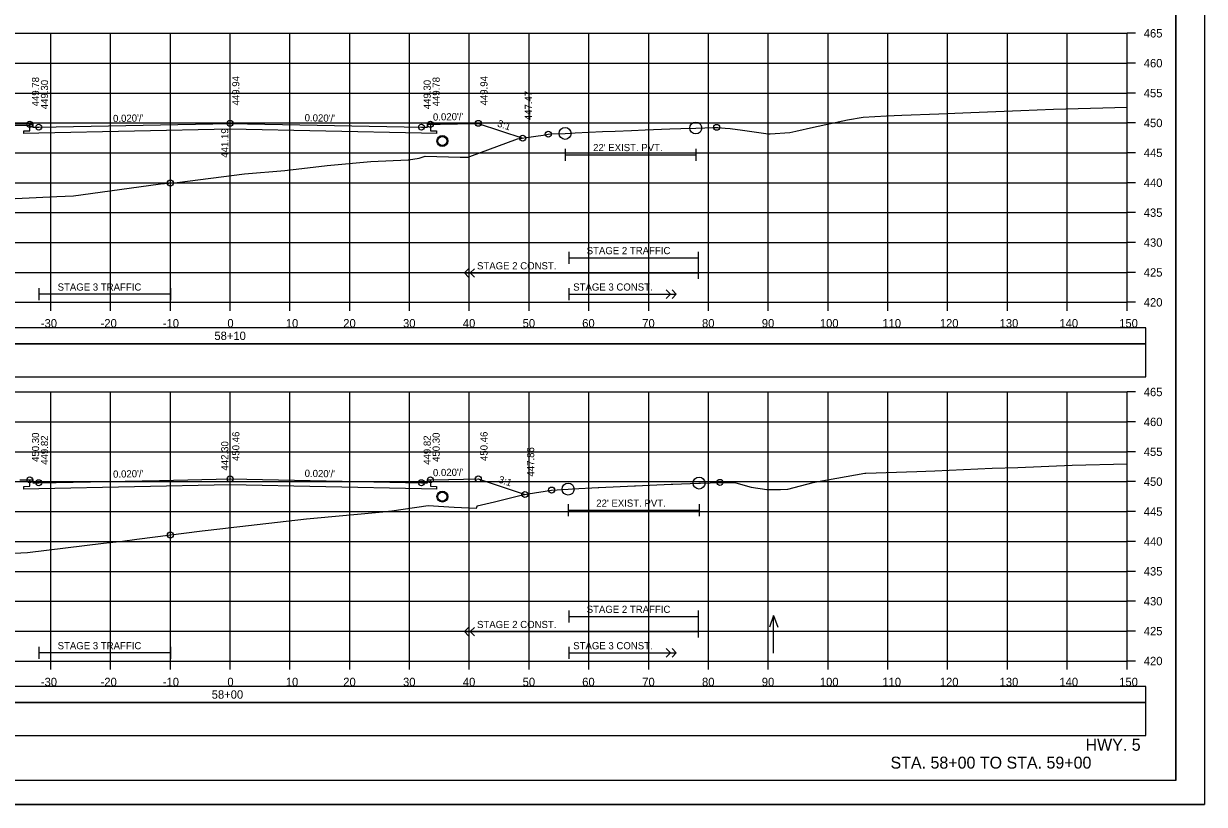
# Model space of a CAD drawing. Extents: x 1371057 to 1372761, y 380005 to 390517.
# Drawn here: x 1371526.3 to 1371723.8, y 384271.8 to 384402.4 of the extents above; entities that cross this region are included whole.
import ezdxf

# ---------------------------------------------------------------- set-up
doc = ezdxf.new("R2010")
doc.units = 0
for name, color, linetype in [('R_Alt Surface', 7, 'Continuous'), ('R_Axis', 7, 'Continuous'), ('R_Axis Annot', 7, 'Continuous'), ('R_Border', 7, 'Continuous'), ('R_Detour', 7, 'Continuous'), ('R_Dimension', 7, 'Continuous'), ('R_Draft', 7, 'Continuous'), ('R_Drive', 7, 'Continuous'), ('R_Exist Surface', 7, 'Continuous'), ('R_Fin Surface', 7, 'Continuous'), ('R_Grid', 7, 'Continuous'), ('R_No Plot', 7, 'Continuous'), ('R_Striping', 7, 'Continuous'), ('R_Water', 7, 'Continuous'), ('R_Water Annot', 7, 'Continuous'), ('R_Xsect Elev', 7, 'Continuous'), ('R_Xsect Slope', 7, 'Continuous')]:
    doc.layers.add(name, color=color, linetype=linetype)

msp = doc.modelspace()

# ---------------------------------------------------------------- linework, layer by layer
at = {"layer": 'R_Alt Surface'}
for points in [[(1371594.37, 384385.6), (1371594.37, 384384.52), (1371595.37, 384384.5), (1371595.37, 384384.07), (1371592.87, 384384.12), (1371560.87, 384384.76), (1371528.87, 384384.12), (1371526.37, 384384.07), (1371526.37, 384384.5), (1371527.37, 384384.52), (1371527.37, 384385.6)], [(1371616.88, 384381.51), (1371616.88, 384379.51)], [(1371638.75, 384381.51), (1371638.75, 384379.51)], [(1371616.88, 384380.51), (1371638.75, 384380.51)], [(1371594.37, 384326.12), (1371594.37, 384325.04), (1371595.37, 384325.02), (1371595.37, 384324.59), (1371592.87, 384324.64), (1371560.87, 384325.28), (1371528.87, 384324.64), (1371526.37, 384324.59), (1371526.37, 384325.02), (1371527.37, 384325.04), (1371527.37, 384326.12)], [(1371617.4, 384322.03), (1371617.4, 384320.03)], [(1371639.29, 384322.03), (1371639.29, 384320.03)], [(1371617.4, 384321.03), (1371639.29, 384321.03)]]:
    msp.add_lwpolyline(points, dxfattribs=at)
at = {"layer": 'R_Axis'}
for p, q in [((1371710.87, 384355.82), (1371710.87, 384400.82)), ((1371712.27, 384400.82), (1371710.87, 384400.82)), ((1371712.27, 384395.82), (1371710.87, 384395.82)), ((1371712.27, 384390.82), (1371710.87, 384390.82)), ((1371712.27, 384385.82), (1371710.87, 384385.82)), ((1371712.27, 384380.82), (1371710.87, 384380.82)), ((1371712.27, 384375.82), (1371710.87, 384375.82)), ((1371712.27, 384370.82), (1371710.87, 384370.82)), ((1371712.27, 384365.82), (1371710.87, 384365.82)), ((1371712.27, 384360.82), (1371710.87, 384360.82)), ((1371410.87, 384355.82), (1371710.87, 384355.82)), ((1371530.87, 384354.42), (1371530.87, 384355.82)), ((1371540.87, 384354.42), (1371540.87, 384355.82)), ((1371550.87, 384354.42), (1371550.87, 384355.82)), ((1371560.87, 384354.42), (1371560.87, 384355.82)), ((1371570.87, 384354.42), (1371570.87, 384355.82)), ((1371580.87, 384354.42), (1371580.87, 384355.82)), ((1371590.87, 384354.42), (1371590.87, 384355.82)), ((1371600.87, 384354.42), (1371600.87, 384355.82)), ((1371610.87, 384354.42), (1371610.87, 384355.82)), ((1371620.87, 384354.42), (1371620.87, 384355.82)), ((1371630.87, 384354.42), (1371630.87, 384355.82)), ((1371640.87, 384354.42), (1371640.87, 384355.82)), ((1371650.87, 384354.42), (1371650.87, 384355.82)), ((1371660.87, 384354.42), (1371660.87, 384355.82)), ((1371670.87, 384354.42), (1371670.87, 384355.82)), ((1371680.87, 384354.42), (1371680.87, 384355.82)), ((1371690.87, 384354.42), (1371690.87, 384355.82)), ((1371700.87, 384354.42), (1371700.87, 384355.82)), ((1371710.87, 384354.42), (1371710.87, 384355.82)), ((1371712.27, 384355.82), (1371710.87, 384355.82)), ((1371710.87, 384295.82), (1371710.87, 384340.82)), ((1371712.27, 384340.82), (1371710.87, 384340.82)), ((1371712.27, 384335.82), (1371710.87, 384335.82)), ((1371712.27, 384330.82), (1371710.87, 384330.82)), ((1371712.27, 384325.82), (1371710.87, 384325.82)), ((1371712.27, 384320.82), (1371710.87, 384320.82)), ((1371712.27, 384315.82), (1371710.87, 384315.82)), ((1371712.27, 384310.82), (1371710.87, 384310.82)), ((1371712.27, 384305.82), (1371710.87, 384305.82)), ((1371712.27, 384300.82), (1371710.87, 384300.82)), ((1371410.87, 384295.82), (1371710.87, 384295.82)), ((1371530.87, 384294.42), (1371530.87, 384295.82)), ((1371540.87, 384294.42), (1371540.87, 384295.82)), ((1371550.87, 384294.42), (1371550.87, 384295.82)), ((1371560.87, 384294.42), (1371560.87, 384295.82)), ((1371570.87, 384294.42), (1371570.87, 384295.82)), ((1371580.87, 384294.42), (1371580.87, 384295.82)), ((1371590.87, 384294.42), (1371590.87, 384295.82)), ((1371600.87, 384294.42), (1371600.87, 384295.82)), ((1371610.87, 384294.42), (1371610.87, 384295.82)), ((1371620.87, 384294.42), (1371620.87, 384295.82)), ((1371630.87, 384294.42), (1371630.87, 384295.82)), ((1371640.87, 384294.42), (1371640.87, 384295.82)), ((1371650.87, 384294.42), (1371650.87, 384295.82)), ((1371660.87, 384294.42), (1371660.87, 384295.82)), ((1371670.87, 384294.42), (1371670.87, 384295.82)), ((1371680.87, 384294.42), (1371680.87, 384295.82)), ((1371690.87, 384294.42), (1371690.87, 384295.82)), ((1371700.87, 384294.42), (1371700.87, 384295.82)), ((1371710.87, 384294.42), (1371710.87, 384295.82)), ((1371712.27, 384295.82), (1371710.87, 384295.82))]:
    msp.add_line(p, q, dxfattribs=at)
at = {"layer": 'R_Border'}
for q in [(1371719.05, 384481.28), (1371402.87, 384275.82)]:
    msp.add_line((1371719.05, 384275.82), q, dxfattribs=at)
at = {"layer": 'R_Detour'}
for points in [[(1371407.72, 384348.87), (1371714.03, 384348.87), (1371714.03, 384351.57), (1371407.72, 384351.57)], [(1371407.72, 384288.87), (1371714.03, 384288.87), (1371714.03, 384291.57), (1371407.72, 384291.57)]]:
    msp.add_lwpolyline(points, close=True, dxfattribs=at)
at = {"layer": 'R_Dimension'}
for points in [[(1371407.72, 384343.34), (1371714.03, 384343.34), (1371714.03, 384348.87), (1371407.72, 384348.87)], [(1371407.72, 384283.34), (1371714.03, 384283.34), (1371714.03, 384288.87), (1371407.72, 384288.87)]]:
    msp.add_lwpolyline(points, close=True, dxfattribs=at)
at = {"layer": 'R_Drive'}
for p, q in [((1371527.38, 384385.35), (1371515.38, 384385.59)), ((1371527.88, 384385.1), (1371527.38, 384385.35))]:
    msp.add_line(p, q, dxfattribs=at)
at = {"layer": 'R_Exist Surface'}
for points in [[(1371514.45, 384372.71), (1371531.86, 384373.52), (1371534.65, 384373.66), (1371537.52, 384374.01), (1371549.25, 384375.62), (1371552.02, 384375.87), (1371563.28, 384377.31), (1371569.99, 384377.85), (1371577.1, 384378.68), (1371584.41, 384379.35), (1371590.66, 384379.64), (1371590.7, 384379.64), (1371592.47, 384379.92), (1371593.5, 384380.25), (1371599.33, 384380.1), (1371600.71, 384380.1), (1371600.98, 384380.22), (1371608.95, 384383.16), (1371610.37, 384383.37), (1371613.24, 384383.8), (1371614.08, 384383.94), (1371614.67, 384383.98), (1371616.88, 384384.08), (1371618.56, 384384.17), (1371623.14, 384384.37), (1371625.26, 384384.47), (1371627.97, 384384.57), (1371630.28, 384384.67), (1371634.43, 384384.83), (1371636.23, 384384.91), (1371638.74, 384384.98), (1371638.75, 384384.98), (1371641.78, 384385.07), (1371642.23, 384385.09), (1371642.45, 384385.09), (1371643.66, 384384.98), (1371644.49, 384384.92), (1371646.56, 384384.63), (1371650.84, 384384.02), (1371651.16, 384384.01), (1371654.48, 384384.2), (1371655.47, 384384.44), (1371658.46, 384385.12), (1371664.11, 384386.32), (1371666.76, 384386.78), (1371670.64, 384387.02), (1371673.22, 384387.1), (1371679.38, 384387.33), (1371684.74, 384387.56), (1371693.08, 384387.91), (1371698.58, 384388.15), (1371704.76, 384388.32), (1371710.87, 384388.47)], [(1371511.64, 384313.21), (1371527, 384313.98), (1371539.68, 384315.54), (1371542.89, 384315.88), (1371545.27, 384316.21), (1371556.19, 384317.57), (1371559.64, 384318.01), (1371560.54, 384318.08), (1371573.62, 384319.63), (1371587.04, 384320.85), (1371587.38, 384320.87), (1371587.38, 384320.87), (1371587.94, 384320.96), (1371593.97, 384321.85), (1371598.34, 384321.55), (1371602.09, 384321.41), (1371602.19, 384321.72), (1371602.19, 384321.76), (1371605.08, 384322.44), (1371609.55, 384323.58), (1371610.69, 384323.76), (1371614.63, 384324.42), (1371617.39, 384324.57), (1371617.4, 384324.57), (1371618.14, 384324.61), (1371622.44, 384324.82), (1371622.55, 384324.83), (1371628.47, 384325.1), (1371628.66, 384325.11), (1371634.65, 384325.38), (1371634.92, 384325.4), (1371639.28, 384325.58), (1371639.28, 384325.58), (1371639.29, 384325.58), (1371639.53, 384325.59), (1371642.77, 384325.7), (1371644.63, 384325.68), (1371645.46, 384325.6), (1371648.03, 384324.91), (1371650.64, 384324.53), (1371652.89, 384324.51), (1371654.12, 384324.58), (1371658.4, 384325.66), (1371659.22, 384325.86), (1371667.03, 384327.24), (1371667.19, 384327.26), (1371667.19, 384327.26), (1371675.74, 384327.52), (1371678.72, 384327.63), (1371688.33, 384328.06), (1371692.59, 384328.17), (1371701.68, 384328.57), (1371710.87, 384328.81)]]:
    msp.add_lwpolyline(points, dxfattribs=at)
at = {"layer": 'R_Fin Surface'}
for points in [[(1371524.37, 384385.66), (1371527.37, 384385.6), (1371527.78, 384385.6), (1371527.87, 384385.6), (1371527.88, 384385.1), (1371528.87, 384385.12), (1371560.87, 384385.76), (1371560.87, 384385.76), (1371592.87, 384385.12), (1371593.26, 384385.11), (1371593.87, 384385.1), (1371593.87, 384385.31), (1371593.87, 384385.6), (1371594.2, 384385.6), (1371594.37, 384385.6), (1371595.98, 384385.63), (1371597.37, 384385.66), (1371598.91, 384385.69), (1371602.37, 384385.76), (1371609.8, 384383.28)], [(1371525.69, 384326.15), (1371527.37, 384326.12), (1371527.38, 384326.12), (1371527.87, 384326.12), (1371527.88, 384325.62), (1371527.88, 384325.62), (1371528.39, 384325.63), (1371528.87, 384325.64), (1371528.87, 384325.64), (1371549.06, 384326.04), (1371560.87, 384326.28), (1371560.97, 384326.27), (1371592.87, 384325.64), (1371592.88, 384325.63), (1371593.87, 384325.62), (1371593.87, 384326.12), (1371594.37, 384326.12), (1371594.48, 384326.12), (1371597.37, 384326.18), (1371597.43, 384326.18), (1371602.37, 384326.28), (1371610.04, 384323.72), (1371610.17, 384323.68)]]:
    msp.add_lwpolyline(points, dxfattribs=at)
at = {"layer": 'R_Grid'}
for p, q in [((1371410.87, 384400.82), (1371710.87, 384400.82)), ((1371530.87, 384355.82), (1371530.87, 384400.82)), ((1371540.87, 384355.82), (1371540.87, 384400.82)), ((1371550.87, 384355.82), (1371550.87, 384400.82)), ((1371560.87, 384355.82), (1371560.87, 384400.82)), ((1371570.87, 384355.82), (1371570.87, 384400.82)), ((1371580.87, 384355.82), (1371580.87, 384400.82)), ((1371590.87, 384355.82), (1371590.87, 384400.82)), ((1371600.87, 384355.82), (1371600.87, 384400.82)), ((1371610.87, 384355.82), (1371610.87, 384400.82)), ((1371620.87, 384355.82), (1371620.87, 384400.82)), ((1371630.87, 384355.82), (1371630.87, 384400.82)), ((1371640.87, 384355.82), (1371640.87, 384400.82)), ((1371650.87, 384355.82), (1371650.87, 384400.82)), ((1371660.87, 384355.82), (1371660.87, 384400.82)), ((1371670.87, 384355.82), (1371670.87, 384400.82)), ((1371680.87, 384355.82), (1371680.87, 384400.82)), ((1371690.87, 384355.82), (1371690.87, 384400.82)), ((1371700.87, 384355.82), (1371700.87, 384400.82)), ((1371710.87, 384355.82), (1371710.87, 384400.82)), ((1371410.87, 384395.82), (1371710.87, 384395.82)), ((1371410.87, 384390.82), (1371710.87, 384390.82)), ((1371410.87, 384385.82), (1371710.87, 384385.82)), ((1371410.87, 384380.82), (1371710.87, 384380.82)), ((1371410.87, 384375.82), (1371710.87, 384375.82)), ((1371410.87, 384370.82), (1371710.87, 384370.82)), ((1371410.87, 384365.82), (1371710.87, 384365.82)), ((1371410.87, 384360.82), (1371710.87, 384360.82)), ((1371410.87, 384355.82), (1371710.87, 384355.82)), ((1371410.87, 384340.82), (1371710.87, 384340.82)), ((1371530.87, 384295.82), (1371530.87, 384340.82)), ((1371540.87, 384295.82), (1371540.87, 384340.82)), ((1371550.87, 384295.82), (1371550.87, 384340.82)), ((1371560.87, 384295.82), (1371560.87, 384340.82)), ((1371570.87, 384295.82), (1371570.87, 384340.82)), ((1371580.87, 384295.82), (1371580.87, 384340.82)), ((1371590.87, 384295.82), (1371590.87, 384340.82)), ((1371600.87, 384295.82), (1371600.87, 384340.82)), ((1371610.87, 384295.82), (1371610.87, 384340.82)), ((1371620.87, 384295.82), (1371620.87, 384340.82)), ((1371630.87, 384295.82), (1371630.87, 384340.82)), ((1371640.87, 384295.82), (1371640.87, 384340.82)), ((1371650.87, 384295.82), (1371650.87, 384340.82)), ((1371660.87, 384295.82), (1371660.87, 384340.82)), ((1371670.87, 384295.82), (1371670.87, 384340.82)), ((1371680.87, 384295.82), (1371680.87, 384340.82)), ((1371690.87, 384295.82), (1371690.87, 384340.82)), ((1371700.87, 384295.82), (1371700.87, 384340.82)), ((1371710.87, 384295.82), (1371710.87, 384340.82)), ((1371410.87, 384335.82), (1371710.87, 384335.82)), ((1371410.87, 384330.82), (1371710.87, 384330.82)), ((1371410.87, 384325.82), (1371710.87, 384325.82)), ((1371410.87, 384320.82), (1371710.87, 384320.82)), ((1371410.87, 384315.82), (1371710.87, 384315.82)), ((1371410.87, 384310.82), (1371710.87, 384310.82)), ((1371410.87, 384305.82), (1371710.87, 384305.82)), ((1371410.87, 384300.82), (1371710.87, 384300.82)), ((1371410.87, 384295.82), (1371710.87, 384295.82))]:
    msp.add_line(p, q, dxfattribs=at)
at = {"layer": 'R_No Plot'}
msp.add_line((1371390.47, 384271.84), (1371723.8, 384271.84), dxfattribs=at)
for points in [[(1371390.46, 384485.17), (1371723.8, 384485.17), (1371723.8, 384271.84), (1371390.46, 384271.84)], [(1371636.79, 384481.28), (1371656.41, 384481.28), (1371656.41, 384471.4), (1371672.52, 384471.4), (1371695.72, 384471.4), (1371695.84, 384443.24), (1371719.05, 384443.24), (1371719.05, 384275.82), (1371402.87, 384275.82), (1371402.87, 384481.28)]]:
    msp.add_lwpolyline(points, close=True, dxfattribs=at)
for centre, radius in [((1371527.37, 384385.6), 0.5), ((1371528.87, 384385.12), 0.5), ((1371560.87, 384385.76), 0.5), ((1371592.87, 384385.12), 0.5), ((1371594.37, 384385.6), 0.5), ((1371602.37, 384385.76), 0.5), ((1371638.75, 384384.98), 1), ((1371642.23, 384385.09), 0.5), ((1371596.37, 384382.8), 0.917), ((1371609.8, 384383.28), 0.5), ((1371614.08, 384383.94), 0.5), ((1371616.88, 384384.08), 1), ((1371550.87, 384375.77), 0.5), ((1371527.37, 384326.12), 0.5), ((1371528.87, 384325.64), 0.5), ((1371560.87, 384326.28), 0.5), ((1371592.87, 384325.64), 0.5), ((1371594.37, 384326.12), 0.5), ((1371602.37, 384326.28), 0.5), ((1371639.29, 384325.58), 1), ((1371642.77, 384325.7), 0.5), ((1371596.37, 384323.32), 0.917), ((1371610.17, 384323.68), 0.5), ((1371614.63, 384324.42), 0.5), ((1371617.4, 384324.57), 1), ((1371550.87, 384316.91), 0.5)]:
    msp.add_circle(centre, radius, dxfattribs=at)
at = {"layer": 'R_Striping'}
for p, q in [((1371617.53, 384364.27), (1371617.53, 384362.27)), ((1371639.16, 384364.27), (1371639.16, 384359.73)), ((1371617.53, 384363.27), (1371639.16, 384363.27)), ((1371600.04, 384360.73), (1371600.75, 384361.43)), ((1371600.04, 384360.73), (1371639.16, 384360.73)), ((1371600.75, 384360.02), (1371600.04, 384360.73)), ((1371601.04, 384360.73), (1371601.75, 384361.43)), ((1371601.75, 384360.02), (1371601.04, 384360.73)), ((1371528.87, 384358.18), (1371528.87, 384356.18)), ((1371550.87, 384358.18), (1371550.87, 384356.18)), ((1371617.49, 384358.18), (1371617.49, 384356.18)), ((1371634.49, 384357.18), (1371633.78, 384357.89)), ((1371635.49, 384357.18), (1371634.78, 384357.89)), ((1371550.87, 384357.18), (1371528.87, 384357.18)), ((1371617.49, 384357.18), (1371635.49, 384357.18)), ((1371633.78, 384356.48), (1371634.49, 384357.18)), ((1371634.78, 384356.48), (1371635.49, 384357.18)), ((1371617.53, 384304.27), (1371617.53, 384302.27)), ((1371639.16, 384304.27), (1371639.16, 384299.73)), ((1371617.53, 384303.27), (1371639.16, 384303.27)), ((1371600.04, 384300.73), (1371600.75, 384301.43)), ((1371600.04, 384300.73), (1371639.16, 384300.73)), ((1371600.75, 384300.02), (1371600.04, 384300.73)), ((1371601.04, 384300.73), (1371601.75, 384301.43)), ((1371601.75, 384300.02), (1371601.04, 384300.73)), ((1371528.87, 384298.18), (1371528.87, 384296.18)), ((1371550.87, 384297.18), (1371528.87, 384297.18)), ((1371550.87, 384298.18), (1371550.87, 384296.18)), ((1371617.49, 384298.18), (1371617.49, 384296.18)), ((1371617.49, 384297.18), (1371635.49, 384297.18)), ((1371634.49, 384297.18), (1371633.78, 384297.89)), ((1371633.78, 384296.48), (1371634.49, 384297.18)), ((1371635.49, 384297.18), (1371634.78, 384297.89)), ((1371634.78, 384296.48), (1371635.49, 384297.18))]:
    msp.add_line(p, q, dxfattribs=at)
at = {"layer": 'R_Water'}
for centre in [(1371596.37, 384382.8), (1371596.37, 384323.32)]:
    msp.add_circle(centre, 0.75, dxfattribs=at)
at = {"layer": 'R_Water Annot'}
for p, q in [((1371651.77, 384303.41), (1371651.07, 384301.49)), ((1371651.77, 384297.13), (1371651.77, 384303.41)), ((1371651.77, 384303.41), (1371652.47, 384301.49))]:
    msp.add_line(p, q, dxfattribs=at)
at = {"layer": 'R_Xsect Elev'}
for p, q in [((1371560.87, 384377.01), (1371560.87, 384387.01)), ((1371560.87, 384318.12), (1371560.87, 384334.68))]:
    msp.add_line(p, q, dxfattribs=at)

# ---------------------------------------------------------------- texts
at = {"layer": 'R_Axis Annot'}
for s, p in [('465', (1371713.67, 384400.12)), ('460', (1371713.67, 384395.12)), ('455', (1371713.67, 384390.12)), ('450', (1371713.67, 384385.12)), ('445', (1371713.67, 384380.12)), ('440', (1371713.67, 384375.12)), ('435', (1371713.67, 384370.12)), ('430', (1371713.67, 384365.12)), ('425', (1371713.67, 384360.12)), ('420', (1371713.67, 384355.12)), ('-30', (1371529.21, 384351.62)), ('-20', (1371539.21, 384351.62)), ('-10', (1371549.61, 384351.62)), ('0', (1371560.41, 384351.62)), ('10', (1371570.18, 384351.62)), ('20', (1371579.79, 384351.62)), ('30', (1371589.79, 384351.62)), ('40', (1371599.79, 384351.62)), ('50', (1371609.79, 384351.62)), ('60', (1371619.75, 384351.62)), ('70', (1371629.79, 384351.62)), ('80', (1371639.79, 384351.62)), ('90', (1371649.79, 384351.62)), ('100', (1371659.5, 384351.62)), ('110', (1371669.95, 384351.62)), ('120', (1371679.56, 384351.62)), ('130', (1371689.56, 384351.62)), ('140', (1371699.56, 384351.62)), ('150', (1371709.56, 384351.62)), ('58+10', (1371558.24, 384349.52)), ('465', (1371713.67, 384340.12)), ('460', (1371713.67, 384335.12)), ('455', (1371713.67, 384330.12)), ('450', (1371713.67, 384325.12)), ('445', (1371713.67, 384320.12)), ('440', (1371713.67, 384315.12)), ('435', (1371713.67, 384310.12)), ('430', (1371713.67, 384305.12)), ('425', (1371713.67, 384300.12)), ('420', (1371713.67, 384295.12)), ('-30', (1371529.21, 384291.62)), ('-20', (1371539.21, 384291.62)), ('-10', (1371549.61, 384291.62)), ('0', (1371560.41, 384291.62)), ('10', (1371570.18, 384291.62)), ('20', (1371579.79, 384291.62)), ('30', (1371589.79, 384291.62)), ('40', (1371599.79, 384291.62)), ('50', (1371609.79, 384291.62)), ('60', (1371619.75, 384291.62)), ('70', (1371629.79, 384291.62)), ('80', (1371639.79, 384291.62)), ('90', (1371649.79, 384291.62)), ('100', (1371659.5, 384291.62)), ('110', (1371669.95, 384291.62)), ('120', (1371679.56, 384291.62)), ('130', (1371689.56, 384291.62)), ('140', (1371699.56, 384291.62)), ('150', (1371709.56, 384291.62)), ('58+00', (1371557.79, 384289.52))]:
    msp.add_text(s, height=1.4, dxfattribs=at).set_placement(p)
at = {"layer": 'R_Draft'}
for s, p in [('HWY. 5', (1371703.93, 384280.81)), ('STA. 58+00 TO STA. 59+00', (1371671.31, 384277.82))]:
    msp.add_text(s, height=2, dxfattribs=at).set_placement(p)
at = {"layer": 'R_Striping'}
for s, p in [('STAGE 2 TRAFFIC', (1371620.5, 384363.87)), ('STAGE 2 CONST.', (1371602.16, 384361.33)), ('STAGE 3 TRAFFIC', (1371532.02, 384357.78)), ('STAGE 3 CONST.', (1371618.25, 384357.78)), ('STAGE 2 TRAFFIC', (1371620.5, 384303.87)), ('STAGE 2 CONST.', (1371602.16, 384301.33)), ('STAGE 3 TRAFFIC', (1371532.02, 384297.78)), ('STAGE 3 CONST.', (1371618.25, 384297.78))]:
    msp.add_text(s, height=1.2, dxfattribs=at).set_placement(p)
at = {"layer": 'R_Water'}
for p in [(1371621.57, 384381.11), (1371622.1, 384321.63)]:
    msp.add_text("22' EXIST. PVT.", height=1.2, dxfattribs=at).set_placement(p)
at = {"layer": 'R_Xsect Elev'}
for s, p in [('449.78', (1371528.92, 384388.6)), ('449.94', (1371562.42, 384388.76)), ('449.78', (1371595.92, 384388.6)), ('449.94', (1371603.92, 384388.76)), ('449.30', (1371530.42, 384388.12)), ('449.30', (1371594.42, 384388.12)), ('447.47', (1371611.35, 384386.28)), ('441.19', (1371560.57, 384380.01)), ('450.30', (1371528.92, 384329.12)), ('450.46', (1371562.42, 384329.28)), ('450.30', (1371595.92, 384329.12)), ('450.46', (1371603.92, 384329.28)), ('449.82', (1371530.42, 384328.64)), ('442.30', (1371560.57, 384327.68)), ('449.82', (1371594.42, 384328.64)), ('447.86', (1371611.72, 384326.68))]:
    msp.add_text(s, height=1.2, rotation=90, dxfattribs=at).set_placement(p)
at = {"layer": 'R_Xsect Slope'}
for s, rotation, p in [("0.020'/'", 1.1457, (1371541.3, 384385.97)), ("0.020'/'", 358.8543, (1371573.32, 384386.11)), ("0.020'/'", 1.1458, (1371594.8, 384386.21)), ('3:1', 341.5631, (1371605.45, 384385.26)), ("0.020'/'", 1.1458, (1371594.8, 384326.72)), ("0.020'/'", 1.1458, (1371541.3, 384326.48)), ("0.020'/'", 358.8543, (1371573.32, 384326.63)), ('3:1', 341.5611, (1371605.64, 384325.71))]:
    msp.add_text(s, height=1.2, rotation=rotation, dxfattribs=at).set_placement(p)

doc.saveas('drawing.dxf')
